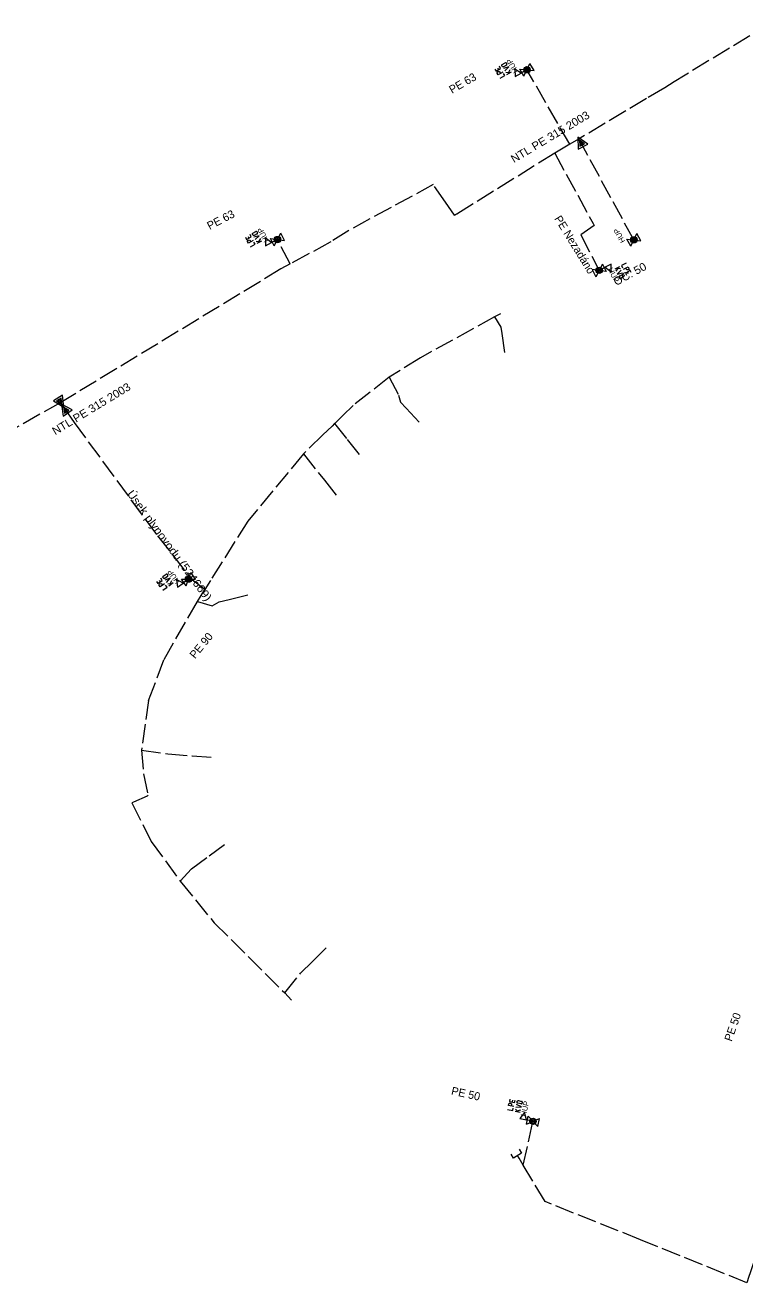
# Model space of a CAD drawing. Extents: x -688140 to -687678, y -1056859 to -1056384.
# Drawn here: x -688002.5 to -687935, y -1056609.6 to -1056491.8 of the extents above; entities that cross this region are included whole.
import ezdxf
from ezdxf.enums import TextEntityAlignment as Align

# ---------------------------------------------------------------- set-up
doc = ezdxf.new("R2010")
doc.units = 0
doc.header["$LTSCALE"] = 0.3
doc.linetypes.add('LONG_DASHED', pattern=[7.5, 6, -1.5])
for name, color, linetype, lineweight in [('12', 7, 'Continuous', 13), ('35', 7, 'LONG_DASHED', 13), ('50', 7, 'LONG_DASHED', 13)]:
    doc.layers.add(name, color=color, linetype=linetype, lineweight=lineweight)
doc.layers.add('15', color=7, linetype='Continuous')

msp = doc.modelspace()

# ---------------------------------------------------------------- linework, layer by layer
at = {"layer": '12'}
for p, q in [((-687957.724, -1056495.494), (-687957.456, -1056495.339)), ((-687957.331, -1056495.556), (-687957.599, -1056495.711)), ((-687955.679, -1056496.606), (-687955.121, -1056495.394)), ((-687954.736, -1056496.061), (-687955.121, -1056495.394)), ((-687958.156, -1056495.847), (-687958.076, -1056495.986)), ((-687957.969, -1056496.19), (-687957.889, -1056496.329)), ((-687957.019, -1056496.276), (-687957.387, -1056496.258)), ((-687957.287, -1056496.431), (-687956.854, -1056496.181)), ((-687957.144, -1056496.279), (-687956.969, -1056495.982)), ((-687956.064, -1056495.939), (-687954.736, -1056496.061)), ((-687955.679, -1056496.606), (-687956.064, -1056495.939)), ((-687955.4, -1056496), (-687955.946, -1056496.315)), ((-687981.546, -1056511.625), (-687981.472, -1056511.767)), ((-687981.375, -1056511.976), (-687981.301, -1056512.118)), ((-687981.099, -1056511.292), (-687980.824, -1056511.149)), ((-687980.709, -1056511.371), (-687980.984, -1056511.514)), ((-687980.429, -1056512.104), (-687980.797, -1056512.07)), ((-687980.704, -1056512.247), (-687980.261, -1056512.017)), ((-687980.555, -1056512.102), (-687980.367, -1056511.813)), ((-687979.461, -1056511.81), (-687978.139, -1056511.99)), ((-687979.106, -1056512.493), (-687979.461, -1056511.81)), ((-687978.8, -1056511.9), (-687979.359, -1056512.19)), ((-687979.106, -1056512.493), (-687978.494, -1056511.307)), ((-687978.139, -1056511.99), (-687978.494, -1056511.307)), ((-687946.038, -1056511.856), (-687944.712, -1056512.01)), ((-687945.669, -1056512.532), (-687946.038, -1056511.856)), ((-687945.669, -1056512.532), (-687945.081, -1056511.334)), ((-687944.712, -1056512.01), (-687945.081, -1056511.334)), ((-687948.323, -1056514.197), (-687948.937, -1056515.383)), ((-687948.63, -1056514.79), (-687948.071, -1056514.5)), ((-687948.323, -1056514.197), (-687947.969, -1056514.881)), ((-687946.725, -1056514.445), (-687947.169, -1056514.675)), ((-687949.291, -1056514.699), (-687948.937, -1056515.383)), ((-687947.969, -1056514.881), (-687949.291, -1056514.699)), ((-687946.875, -1056514.591), (-687947.063, -1056514.879)), ((-687947, -1056514.588), (-687946.633, -1056514.623)), ((-687946.722, -1056515.322), (-687946.446, -1056515.179)), ((-687946.331, -1056515.401), (-687946.607, -1056515.544)), ((-687946.055, -1056514.718), (-687946.128, -1056514.575)), ((-687945.884, -1056515.068), (-687945.958, -1056514.926)), ((-687989.897, -1056543.842), (-687989.804, -1056543.971)), ((-687989.503, -1056543.448), (-687989.251, -1056543.267)), ((-687989.105, -1056543.47), (-687989.357, -1056543.651)), ((-687988.848, -1056544.171), (-687988.703, -1056543.858)), ((-687987.807, -1056543.725), (-687986.473, -1056543.715)), ((-687987.358, -1056544.351), (-687987.807, -1056543.725)), ((-687987.14, -1056543.72), (-687987.652, -1056544.088)), ((-687987.358, -1056544.351), (-687986.922, -1056543.089)), ((-687986.473, -1056543.715), (-687986.922, -1056543.089)), ((-687989.678, -1056544.164), (-687989.584, -1056544.294)), ((-687988.723, -1056544.156), (-687989.092, -1056544.174)), ((-687988.975, -1056544.337), (-687988.569, -1056544.045)), ((-687956.853, -1056592.925), (-687956.888, -1056593.081)), ((-687956.759, -1056592.546), (-687956.794, -1056592.703)), ((-687956.21, -1056593.631), (-687956.47, -1056593.368)), ((-687956.305, -1056593.548), (-687955.975, -1056593.447)), ((-687955.954, -1056592.888), (-687956.257, -1056592.821)), ((-687956.203, -1056592.577), (-687955.9, -1056592.644)), ((-687956.513, -1056593.564), (-687956.025, -1056593.672)), ((-687955.445, -1056594.778), (-687955.279, -1056594.026)), ((-687955.445, -1056594.778), (-687954.215, -1056594.262)), ((-687954.83, -1056594.52), (-687955.445, -1056594.384)), ((-687955.279, -1056594.026), (-687954.381, -1056595.014)), ((-687954.381, -1056595.014), (-687954.215, -1056594.262))]:
    msp.add_line(p, q, dxfattribs=at)
for points in [[(-687957.599, -1056495.711), (-687957.625, -1056495.726), (-687957.661, -1056495.724), (-687957.707, -1056495.704), (-687957.727, -1056495.669), (-687957.752, -1056495.626), (-687957.767, -1056495.6), (-687957.753, -1056495.545), (-687957.745, -1056495.518), (-687957.724, -1056495.494)], [(-687957.331, -1056495.556), (-687957.296, -1056495.536), (-687957.289, -1056495.509), (-687957.283, -1056495.459), (-687957.294, -1056495.419), (-687957.319, -1056495.376), (-687957.334, -1056495.35), (-687957.389, -1056495.335), (-687957.416, -1056495.328), (-687957.456, -1056495.339)], [(-687958.411, -1056495.925), (-687958.301, -1056496.116), (-687957.868, -1056495.866), (-687957.988, -1056495.658)], [(-687958.186, -1056496.315), (-687958.193, -1056496.262), (-687958.144, -1056496.187), (-687958.109, -1056496.167), (-687958.011, -1056496.157), (-687957.969, -1056496.19)], [(-687957.673, -1056496.204), (-687958.106, -1056496.454), (-687958.186, -1056496.315)], [(-687957.911, -1056496.791), (-687957.478, -1056496.541), (-687957.593, -1056496.342)], [(-687957.477, -1056496.102), (-687957.114, -1056495.731), (-687957.607, -1056495.877)], [(-687981.804, -1056511.692), (-687981.703, -1056511.887), (-687981.259, -1056511.656), (-687981.37, -1056511.444)], [(-687981.597, -1056512.091), (-687981.602, -1056512.038), (-687981.55, -1056511.965), (-687981.514, -1056511.947), (-687981.416, -1056511.941), (-687981.375, -1056511.976)], [(-687981.079, -1056512.003), (-687981.523, -1056512.233), (-687981.597, -1056512.091)], [(-687981.343, -1056512.579), (-687980.9, -1056512.349), (-687981.006, -1056512.145)], [(-687980.984, -1056511.514), (-687981.011, -1056511.527), (-687981.047, -1056511.523), (-687981.092, -1056511.502), (-687981.11, -1056511.466), (-687981.133, -1056511.422), (-687981.147, -1056511.395), (-687981.13, -1056511.341), (-687981.121, -1056511.314), (-687981.099, -1056511.292)], [(-687980.88, -1056511.91), (-687980.501, -1056511.555), (-687981, -1056511.679)], [(-687980.709, -1056511.371), (-687980.674, -1056511.352), (-687980.665, -1056511.325), (-687980.657, -1056511.276), (-687980.666, -1056511.236), (-687980.69, -1056511.191), (-687980.703, -1056511.165), (-687980.757, -1056511.148), (-687980.784, -1056511.139), (-687980.824, -1056511.149)], [(-687946.086, -1056514.114), (-687946.53, -1056514.344), (-687946.424, -1056514.548)], [(-687946.35, -1056514.69), (-687945.906, -1056514.46), (-687945.833, -1056514.603)], [(-687946.55, -1056514.783), (-687946.93, -1056515.137), (-687946.431, -1056515.014)], [(-687946.722, -1056515.322), (-687946.757, -1056515.34), (-687946.766, -1056515.367), (-687946.774, -1056515.417), (-687946.764, -1056515.457), (-687946.741, -1056515.501), (-687946.728, -1056515.528), (-687946.674, -1056515.545), (-687946.647, -1056515.553), (-687946.607, -1056515.544)], [(-687946.446, -1056515.179), (-687946.42, -1056515.166), (-687946.384, -1056515.169), (-687946.339, -1056515.191), (-687946.32, -1056515.227), (-687946.297, -1056515.271), (-687946.284, -1056515.298), (-687946.301, -1056515.352), (-687946.309, -1056515.379), (-687946.331, -1056515.401)], [(-687945.626, -1056515.002), (-687945.727, -1056514.807), (-687946.171, -1056515.037), (-687946.061, -1056515.25)], [(-687945.833, -1056514.603), (-687945.828, -1056514.656), (-687945.88, -1056514.728), (-687945.916, -1056514.747), (-687946.014, -1056514.753), (-687946.055, -1056514.718)], [(-687990.143, -1056543.944), (-687990.015, -1056544.123), (-687989.609, -1056543.831), (-687989.749, -1056543.637)], [(-687989.357, -1056543.651), (-687989.381, -1056543.668), (-687989.417, -1056543.669), (-687989.465, -1056543.654), (-687989.488, -1056543.622), (-687989.518, -1056543.581), (-687989.535, -1056543.557), (-687989.526, -1056543.501), (-687989.521, -1056543.473), (-687989.503, -1056543.448)], [(-687989.197, -1056544.028), (-687988.872, -1056543.622), (-687989.348, -1056543.817)], [(-687989.105, -1056543.47), (-687989.073, -1056543.446), (-687989.068, -1056543.418), (-687989.067, -1056543.368), (-687989.082, -1056543.33), (-687989.112, -1056543.29), (-687989.129, -1056543.265), (-687989.185, -1056543.256), (-687989.213, -1056543.251), (-687989.251, -1056543.267)], [(-687989.881, -1056544.31), (-687989.894, -1056544.258), (-687989.852, -1056544.179), (-687989.819, -1056544.155), (-687989.723, -1056544.135), (-687989.678, -1056544.164)], [(-687989.381, -1056544.148), (-687989.787, -1056544.44), (-687989.881, -1056544.31)], [(-687989.56, -1056544.757), (-687989.154, -1056544.465), (-687989.288, -1056544.278)], [(-687957.216, -1056593.408), (-687956.728, -1056593.516), (-687956.678, -1056593.291)], [(-687956.644, -1056593.135), (-687957.132, -1056593.027), (-687957.097, -1056592.871)], [(-687957.097, -1056592.871), (-687957.067, -1056592.826), (-687956.98, -1056592.805), (-687956.941, -1056592.813), (-687956.862, -1056592.872), (-687956.853, -1056592.925)], [(-687957, -1056592.432), (-687957.047, -1056592.646), (-687956.559, -1056592.754), (-687956.507, -1056592.52)], [(-687956.431, -1056593.193), (-687955.912, -1056593.164), (-687956.375, -1056592.939)], [(-687956.257, -1056592.821), (-687956.286, -1056592.815), (-687956.311, -1056592.789), (-687956.331, -1056592.743), (-687956.323, -1056592.704), (-687956.312, -1056592.656), (-687956.306, -1056592.626), (-687956.258, -1056592.596), (-687956.234, -1056592.581), (-687956.203, -1056592.577)], [(-687955.954, -1056592.888), (-687955.915, -1056592.897), (-687955.891, -1056592.882), (-687955.853, -1056592.849), (-687955.835, -1056592.812), (-687955.824, -1056592.764), (-687955.817, -1056592.734), (-687955.848, -1056592.687), (-687955.863, -1056592.663), (-687955.9, -1056592.644)], [(-687956.129, -1056597.125), (-687955.902, -1056597.503), (-687956.658, -1056597.957), (-687956.885, -1056597.579)]]:
    msp.add_lwpolyline(points, dxfattribs=at)
for points in [[(-687955.946, -1056496.315), (-687956.538, -1056495.929), (-687956.5, -1056496.635)], [(-687949.704, -1056502.95), (-687950.633, -1056502.301), (-687950.59, -1056503.434)], [(-687950.009, -1056502.923), (-687950.473, -1056502.595), (-687950.448, -1056503.163)], [(-687950.164, -1056502.911), (-687950.394, -1056502.74), (-687950.375, -1056503.026)], [(-687979.359, -1056512.19), (-687979.933, -1056511.779), (-687979.927, -1056512.486)], [(-687948.071, -1056514.5), (-687947.497, -1056514.913), (-687947.502, -1056514.206)], [(-687999.817, -1056527.014), (-687998.847, -1056527.601), (-687998.964, -1056526.473)], [(-687999.511, -1056527.021), (-687999.026, -1056527.318), (-687999.088, -1056526.753)], [(-687999.355, -1056527.023), (-687999.115, -1056527.178), (-687999.153, -1056526.895)], [(-687998.057, -1056527.869), (-687999.048, -1056527.319), (-687998.889, -1056528.441)], [(-687998.363, -1056527.873), (-687998.858, -1056527.595), (-687998.775, -1056528.157)], [(-687998.518, -1056527.877), (-687998.765, -1056527.731), (-687998.716, -1056528.013)], [(-687987.652, -1056544.088), (-687988.279, -1056543.763), (-687988.171, -1056544.461)], [(-687955.445, -1056594.384), (-687955.621, -1056593.7), (-687956.07, -1056594.245)]]:
    msp.add_lwpolyline(points, close=True, dxfattribs=at)
for centre, radius in [((-687955.4, -1056496), 0.297), ((-687955.4, -1056496), 0.223), ((-687955.4, -1056496), 0.223), ((-687955.4, -1056496), 0.112), ((-687978.8, -1056511.9), 0.297), ((-687978.8, -1056511.9), 0.223), ((-687978.8, -1056511.9), 0.223), ((-687978.8, -1056511.9), 0.112), ((-687945.375, -1056511.933), 0.297), ((-687945.375, -1056511.933), 0.223), ((-687945.375, -1056511.933), 0.223), ((-687945.375, -1056511.933), 0.112), ((-687948.63, -1056514.79), 0.297), ((-687948.63, -1056514.79), 0.223), ((-687948.63, -1056514.79), 0.223), ((-687948.63, -1056514.79), 0.112), ((-687987.14, -1056543.72), 0.297), ((-687987.14, -1056543.72), 0.223), ((-687987.14, -1056543.72), 0.223), ((-687987.14, -1056543.72), 0.112), ((-687954.83, -1056594.52), 0.297), ((-687954.83, -1056594.52), 0.223), ((-687954.83, -1056594.52), 0.223), ((-687954.83, -1056594.52), 0.112)]:
    msp.add_circle(centre, radius, dxfattribs=at)
at = {"layer": '35'}
msp.add_line((-687998.759, -1056527.739), (-687999.12, -1056527.17), dxfattribs=at)
for points in [[(-687934.92, -1056483.379), (-687934.48, -1056484.1), (-687931.57, -1056488.93), (-687931.05, -1056489.78), (-687930.64, -1056490.47), (-687940.574, -1056496.498), (-687941.6, -1056497.12), (-687942.464, -1056497.696), (-687944.2, -1056498.69), (-687950.55, -1056502.49), (-687951.37, -1056502.98), (-687952.8, -1056503.81), (-687962, -1056509.53), (-687962.18, -1056509.64), (-687962.19, -1056509.625), (-687963.04, -1056508.39), (-687964.19, -1056506.75), (-687972.1, -1056511.04), (-687973.789, -1056512.111), (-687973.85, -1056512.15), (-687977.61, -1056514.19), (-687978.48, -1056514.66), (-687999.12, -1056527.17), (-688005.94, -1056531)], [(-687957.89, -1056518.85), (-687958.43, -1056519.15), (-687965.39, -1056522.98), (-687968.32, -1056524.81), (-687971.69, -1056527.45), (-687972.663, -1056528.395), (-687973.424, -1056529.134), (-687973.44, -1056529.15), (-687973.669, -1056529.371), (-687974.529, -1056530.201), (-687976.37, -1056531.98), (-687981.58, -1056538.3), (-687985.09, -1056543.84), (-687985.6, -1056544.68)], [(-687998.759, -1056527.739), (-687997.87, -1056529.03), (-687990.05, -1056539.67), (-687986.77, -1056543.81)], [(-687990.89, -1056555.08), (-687989.44, -1056551.26), (-687986.3, -1056545.81), (-687985.6, -1056544.68), (-687986.77, -1056543.81)], [(-687990.89, -1056555.08), (-687991.54, -1056559.73), (-687991.37, -1056561.97), (-687990.92, -1056564), (-687991.01, -1056564.04), (-687992.29, -1056564.62), (-687992.45, -1056564.69), (-687990.64, -1056568.29), (-687987.91, -1056572.03), (-687984.74, -1056575.91), (-687978.11, -1056582.49), (-687977.47, -1056583.16)], [(-687921.01, -1056570.47), (-687921.99, -1056576.46), (-687922.13, -1056577.25), (-687922.32, -1056578.35), (-687924.34, -1056583.3), (-687925.62, -1056586.17), (-687930.67, -1056599.14), (-687931.44, -1056600.9), (-687931.469, -1056600.974), (-687932.74, -1056604.24), (-687933.15, -1056605.26), (-687934.17, -1056607.86), (-687934.46, -1056608.712), (-687934.582, -1056609.07), (-687934.78, -1056609.65), (-687944.75, -1056605.61), (-687953.7, -1056602.04), (-687955.74, -1056598.63), (-687956.136, -1056597.968), (-687956.28, -1056597.73)]]:
    msp.add_lwpolyline(points, dxfattribs=at)
at = {"layer": '50'}
for p, q in [((-687951.37, -1056502.98), (-687955.4, -1056496)), ((-687977.61, -1056514.19), (-687978.8, -1056511.9)), ((-687955.74, -1056598.63), (-687954.83, -1056594.52))]:
    msp.add_line(p, q, dxfattribs=at)
for points in [[(-687945.375, -1056511.933), (-687950.389, -1056502.749), (-687950.55, -1056502.49)], [(-687952.8, -1056503.81), (-687949.2, -1056510.39), (-687949.1, -1056510.57), (-687950.36, -1056511.45), (-687948.63, -1056514.79)], [(-687958.43, -1056519.15), (-687957.85, -1056520.1), (-687957.76, -1056520.7), (-687957.463, -1056522.678)], [(-687968.32, -1056524.81), (-687967.44, -1056526.48), (-687967.25, -1056527.14), (-687966.73, -1056527.7), (-687965.369, -1056529.166)], [(-687973.44, -1056529.15), (-687972.25, -1056530.63), (-687970.997, -1056532.189)], [(-687976.37, -1056531.98), (-687974.4, -1056534.45), (-687973.153, -1056536.014)], [(-687986.3, -1056545.81), (-687984.92, -1056546.22), (-687984.26, -1056545.86), (-687983.33, -1056545.63), (-687981.388, -1056545.15)], [(-687991.54, -1056559.73), (-687989.07, -1056560.09), (-687986.8, -1056560.27), (-687984.806, -1056560.428)], [(-687987.91, -1056572.03), (-687986.86, -1056570.86), (-687985.21, -1056569.64), (-687983.602, -1056568.451)], [(-687978.11, -1056582.49), (-687976.64, -1056580.63), (-687975.51, -1056579.53), (-687974.077, -1056578.135)]]:
    msp.add_lwpolyline(points, dxfattribs=at)

# ---------------------------------------------------------------- texts
at = {"layer": '12', "width": 0.9}
for rotation, p in [(120, (-687956.55, -1056495.509)), (117.456, (-687979.927, -1056511.359)), (118.642, (-687946.512, -1056511.415)), (297.381, (-687947.504, -1056515.333)), (125.696, (-687988.333, -1056543.345)), (77.516, (-687955.346, -1056593.381))]:
    msp.add_text('HUP', height=0.5, rotation=rotation, dxfattribs=at).set_placement(p, align=Align.CENTER)
at = {"layer": '15'}
for s, rotation, p in [('PE 63', 30.001, (-687962.431, -1056498.252)), ('PE 63', 27.459, (-687985.157, -1056511.009)), ('PE Nezadáno', 301.701, (-687952.862, -1056509.941)), ('PE 90', 50.599, (-687986.527, -1056551.23)), ('PE 50', 70.643, (-687936.204, -1056587.088)), ('PE 50', 347.515, (-687962.55, -1056591.997))]:
    msp.add_text(s, height=0.75, rotation=rotation, dxfattribs=at).set_placement(p)
for s, rotation, width, p in [('NTL PE 315 2003', 30.897, 1.05, (-687956.625, -1056504.751)), ('OC. 50', 28.64, 1.05, (-687947.031, -1056516.258)), ('NTL PE 315 2003', 31.22, 1.05, (-687999.643, -1056530.249)), ('Úsek plynovodu (524669)', 306.314, 1.1, (-687992.95, -1056535.73))]:
    msp.add_text(s, height=0.75, rotation=rotation, dxfattribs=dict(at, width=width)).set_placement(p)

doc.saveas('drawing.dxf')
